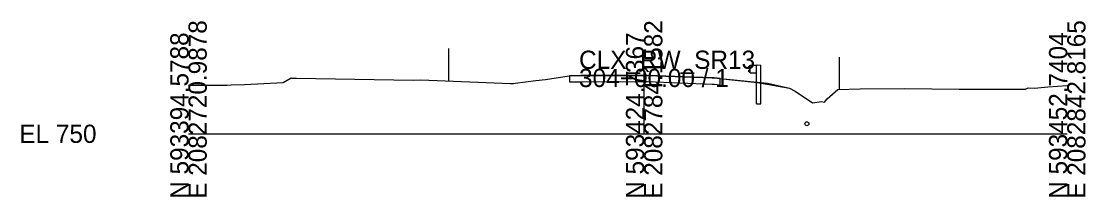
# Model space of a CAD drawing. Extents: x -26 to 2138, y -10 to 4518.
# Drawn here: x 974.3 to 1137.8, y 3990.3 to 4017.3 of the extents above; entities that cross this region are included whole.
import ezdxf

# ---------------------------------------------------------------- set-up
doc = ezdxf.new("R2010")
doc.units = 0
for name, color, linetype in [('GK_Cells', 7, 'Continuous'), ('MD_X_Asphalt_Pavement', 7, 'Continuous'), ('RD_P_Cells', 7, 'Continuous'), ('RW_X_Esmt_SH', 7, 'Continuous'), ('UT_X_Water', 7, 'Continuous'), ('XS_P_Finished_Grade', 7, 'Continuous'), ('XS_X_Ground_Line', 7, 'Continuous')]:
    doc.layers.add(name, color=color, linetype=linetype)

msp = doc.modelspace()

# ---------------------------------------------------------------- linework, layer by layer
at = {"layer": 'GK_Cells'}
for p, q in [((1070, 4000), (1070, 4010)), ((1000, 4000), (1070, 4000)), ((1070, 4000), (1135, 4000))]:
    msp.add_line(p, q, dxfattribs=at)
at = {"layer": 'MD_X_Asphalt_Pavement'}
msp.add_lwpolyline([(1060.28, 4008.96), (1058.55, 4008.94), (1058.55, 4007.98), (1060.28, 4008), (1060.29, 4008), (1070.28, 4008.03), (1070.53, 4008.03), (1080.43, 4007.65), (1080.75, 4007.63), (1080.77, 4007.63), (1081.68, 4007.56), (1081.68, 4008.51), (1080.77, 4008.59), (1080.75, 4008.59), (1080.43, 4008.6), (1070.53, 4008.99), (1070.28, 4008.99), (1060.29, 4008.96), (1060.28, 4008.96)], dxfattribs=at)
at = {"layer": 'RD_P_Cells'}
for p, q in [((1086.03, 4010.37), (1086.19, 4010.48)), ((1086.24, 4010.1), (1086.03, 4010.24)), ((1086.03, 4009.74), (1086.24, 4009.88)), ((1086.19, 4010.48), (1086.28, 4010.5)), ((1086.27, 4009.99), (1086.27, 4010.04)), ((1086.27, 4009.94), (1086.27, 4009.99)), ((1086.28, 4009.4), (1086.28, 4010.58)), ((1086.28, 4010.58), (1087.28, 4010.58)), ((1087.28, 4010.58), (1087.36, 4010.62)), ((1087.28, 4004.62), (1087.28, 4010.58)), ((1087.36, 4010.62), (1087.9, 4010.54)), ((1087.9, 4010.54), (1087.95, 4010.52)), ((1087.95, 4004.62), (1087.95, 4010.52)), ((1086.19, 4009.49), (1086.03, 4009.61)), ((1086.28, 4009.48), (1086.19, 4009.49)), ((1086.28, 4009.4), (1087.28, 4009.4)), ((1087.28, 4004.62), (1087.95, 4004.62))]:
    msp.add_line(p, q, dxfattribs=at)
for points in [[(1086.26, 4010.02), (1086.26, 4009.96), (1086.24, 4009.96), (1086.24, 4010.02)], [(1086.26, 4010.05), (1086.26, 4009.93), (1086.27, 4009.93), (1086.27, 4010.05)]]:
    msp.add_lwpolyline(points, close=True, dxfattribs=at)
for centre, start, end in [((1086.08, 4010.31), 125.2323, 235.038), ((1086.19, 4010.04), 0, 55.038), ((1086.19, 4009.94), 304.962, 0), ((1086.08, 4009.67), 125.2323, 235.038)]:
    msp.add_arc(centre, 0.0781, start, end, dxfattribs=at)
at = {"layer": 'RW_X_Esmt_SH'}
for p, q in [((1040, 4008.12), (1040, 4013.12)), ((1100, 4006.82), (1100, 4011.82))]:
    msp.add_line(p, q, dxfattribs=at)
at = {"layer": 'UT_X_Water'}
msp.add_circle((1095, 4001.55), 0.3, dxfattribs=at)
at = {"layer": 'XS_P_Finished_Grade'}
for p, q in [((1081.68, 4008.51), (1088.95, 4007.79)), ((1088.95, 4007.79), (1092.33, 4007.02))]:
    msp.add_line(p, q, dxfattribs=at)
at = {"layer": 'XS_X_Ground_Line'}
msp.add_lwpolyline([(1000, 4007.47), (1005.94, 4007.5), (1006.55, 4007.52), (1008.62, 4007.57), (1014.53, 4007.91), (1015.77, 4008.59), (1015.77, 4008.59), (1015.83, 4008.58), (1015.86, 4008.58), (1016.58, 4008.56), (1034.5, 4008.27), (1035.67, 4008.29), (1049.45, 4007.76), (1049.92, 4007.75), (1050.16, 4007.78), (1053.36, 4008.18), (1054.83, 4008.36), (1058.46, 4008.93), (1058.55, 4008.94), (1060.28, 4008.96), (1060.29, 4008.96), (1070.28, 4008.99), (1070.53, 4008.99), (1080.43, 4008.6), (1080.75, 4008.59), (1080.77, 4008.59), (1081.68, 4008.51), (1083.45, 4008.32), (1087.43, 4007.89), (1092.33, 4007.02), (1093.21, 4006.54), (1095.88, 4004.76), (1097.24, 4004.95), (1097.7, 4004.88), (1098.13, 4005.37), (1099.76, 4006.82), (1103.18, 4006.92), (1110.02, 4006.98), (1118.4, 4006.88), (1118.6, 4006.88), (1120.14, 4006.88), (1122.43, 4006.88), (1126.46, 4006.88), (1128.6, 4006.88), (1129.02, 4007.06), (1129.96, 4007.02), (1132.01, 4007.24), (1135, 4007.43)], dxfattribs=at)

# ---------------------------------------------------------------- texts
msp.add_text('-', height=0.0001).set_placement((1000, 4000))
at = {"layer": 'GK_Cells'}
for s, p in [('E 2082720.9878', (1002.8, 3990)), ('E 2082784.1582', (1072.8, 3990)), ('E 2082842.8165', (1137.8, 3990)), ('N 593394.5788', (1000, 3990)), ('N 593424.7367', (1070, 3990)), ('N 593452.7404', (1135, 3990))]:
    msp.add_text(s, height=2.8, rotation=90, dxfattribs=at).set_placement(p)
for s, p in [('CLX_RW_SR13', (1060, 4010)), ('304+00.00 / 1', (1060, 4007.2)), ('EL 750', (974, 3998.6))]:
    msp.add_text(s, height=2.8, dxfattribs=at).set_placement(p)

doc.saveas('drawing.dxf')
